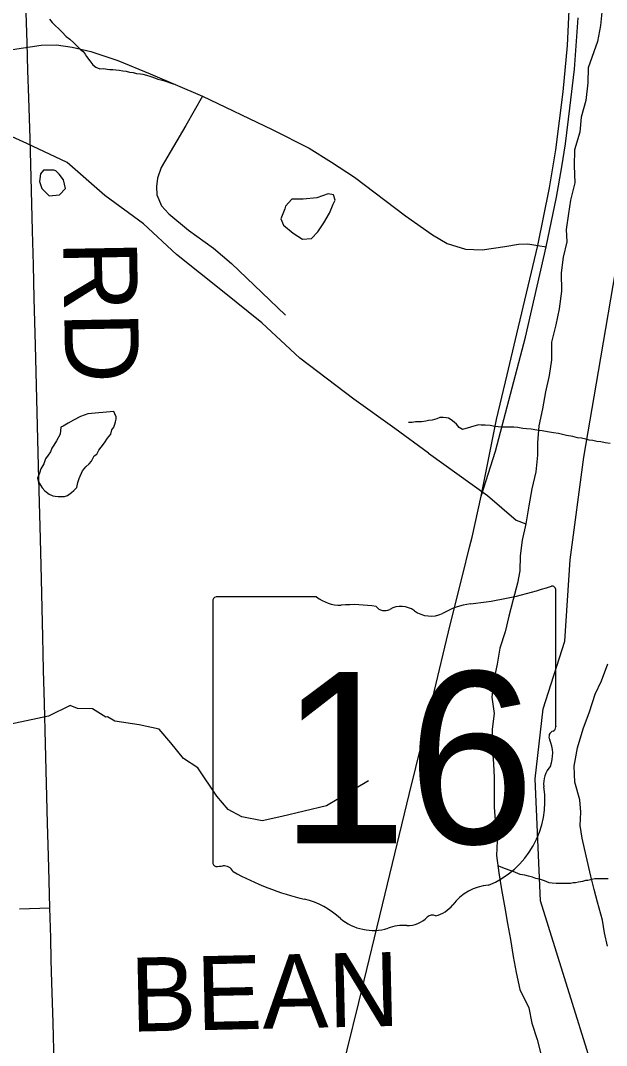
# Model space of a CAD drawing. Extents: x -6.1 to 38, y -7.7 to 22.
# Drawn here: x 4.306 to 4.757, y 15.687 to 16.475 of the extents above; entities that cross this region are included whole.
import ezdxf

# ---------------------------------------------------------------- set-up
doc = ezdxf.new("R2010")
doc.units = 0
for name, color, linetype in [('GM_X_Corporation', 7, 'Continuous'), ('GM_X_County_Road', 7, 'Continuous'), ('GM_X_County_Road_Text', 7, 'Continuous'), ('GM_X_Major_River', 7, 'Continuous'), ('GM_X_Minor_Lake', 7, 'Continuous'), ('GM_X_Minor_River', 7, 'Continuous'), ('GM_X_State_Location', 7, 'Continuous'), ('GM_X_State_Route', 7, 'Continuous'), ('GM_X_State_Shield', 7, 'Continuous'), ('GM_X_Township_Road', 7, 'Continuous'), ('GM_X_Township_Road_Text', 7, 'Continuous')]:
    doc.layers.add(name, color=color, linetype=linetype)

msp = doc.modelspace()

# ---------------------------------------------------------------- linework, layer by layer
at = {"layer": 'GM_X_Corporation'}
for points in [[(4.28061, 14.99995), (5.0967, 14.97556), (5.0486, 15.07962), (5.00913, 15.14194), (4.9572, 15.18142), (4.93228, 15.20843), (4.89329, 15.26962), (4.86101, 15.32821), (4.83828, 15.37125), (4.81915, 15.43553), (4.80087, 15.50695), (4.76612, 15.60524), (4.7059, 15.79844), (4.70175, 15.89192), (4.708, 15.94593), (4.72462, 15.99787), (4.72878, 16.06019), (4.73919, 16.13913), (4.75046, 16.20506), (4.78077, 16.38218), (4.78909, 16.45229), (4.83333, 16.6969)], [(5.74746, 14.95956), (5.18977, 14.97327), (5.0967, 14.97556), (5.0486, 15.07962), (5.00913, 15.14194), (4.9572, 15.18142), (4.93228, 15.20843), (4.89329, 15.26962), (4.86101, 15.32821), (4.83828, 15.37125), (4.81915, 15.43553), (4.80087, 15.50695), (4.76612, 15.60524), (4.7059, 15.79844), (4.70175, 15.89192), (4.708, 15.94593), (4.72462, 15.99787), (4.72878, 16.06019), (4.73919, 16.13913), (4.75046, 16.20506), (4.78077, 16.38218), (4.78909, 16.45229), (4.83333, 16.6969)]]:
    msp.add_lwpolyline(points, dxfattribs=at)
at = {"layer": 'GM_X_County_Road'}
for points in [[(4.33216, 15.67345), (4.33127, 15.70451), (4.33039, 15.73557), (4.3299, 15.75276), (4.32941, 15.76995), (4.32878, 15.79287), (4.32792, 15.82393), (4.32746, 15.841), (4.32699, 15.85806), (4.32615, 15.88853), (4.3253, 15.91899), (4.32459, 15.95005), (4.324, 15.97555), (4.32341, 16.00105), (4.3229, 16.0232), (4.32238, 16.04536), (4.32157, 16.07642), (4.32084, 16.10426), (4.32011, 16.1321), (4.31931, 16.16316), (4.31849, 16.19422), (4.31768, 16.22527), (4.31722, 16.24309), (4.31675, 16.2609), (4.31613, 16.28689), (4.31551, 16.31289), (4.31465, 16.34395), (4.31409, 16.364), (4.31353, 16.38405), (4.31257, 16.41511), (4.31192, 16.43622), (4.31126, 16.45734), (4.31048, 16.48066)], [(4.30002, 16.45221), (4.32205, 16.45572), (4.33381, 16.45579), (4.34597, 16.45406), (4.36018, 16.45075), (4.38106, 16.44372), (4.40589, 16.4337), (4.44615, 16.41641), (4.49966, 16.39096), (4.5281, 16.37638), (4.54515, 16.36572), (4.56291, 16.35412), (4.60225, 16.32448), (4.62287, 16.30981), (4.63409, 16.30318), (4.64837, 16.29885), (4.66111, 16.29834), (4.67846, 16.30088), (4.68905, 16.30263), (4.69609, 16.3031), (4.70391, 16.30184), (4.71026, 16.30082)]]:
    msp.add_lwpolyline(points, dxfattribs=at)
at = {"layer": 'GM_X_Major_River'}
for points in [[(4.75336, 16.48356), (4.75194, 16.47066), (4.74975, 16.45851), (4.74245, 16.43815)], [(4.74245, 16.43815), (4.74217, 16.42678), (4.74077, 16.41312), (4.73709, 16.40021), (4.73605, 16.38883), (4.73201, 16.37516), (4.73173, 16.36303), (4.73222, 16.34976), (4.72892, 16.33647), (4.7275, 16.32623), (4.7257, 16.31409), (4.72616, 16.30461), (4.72323, 16.29284), (4.72182, 16.28071), (4.72193, 16.26668), (4.72016, 16.25303), (4.71761, 16.24088), (4.71432, 16.22759), (4.71443, 16.21394), (4.71264, 16.2018), (4.70972, 16.18928), (4.70755, 16.17637), (4.70464, 16.16309), (4.70361, 16.15019), (4.70369, 16.14071), (4.70228, 16.12782), (4.69936, 16.11491), (4.69682, 16.10163), (4.69467, 16.08797), (4.69175, 16.07544), (4.69034, 16.0633), (4.69005, 16.05193), (4.68824, 16.04244), (4.68494, 16.02991), (4.68164, 16.017), (4.67872, 16.00485), (4.67466, 15.99232), (4.67249, 15.98017), (4.66995, 15.96803), (4.66854, 15.95475), (4.67016, 15.94225), (4.66875, 15.93011), (4.66885, 15.91723), (4.66972, 15.90359), (4.67018, 15.89298), (4.67037, 15.87023), (4.67124, 15.85697), (4.67247, 15.84447), (4.67219, 15.8331), (4.67381, 15.81984), (4.67581, 15.80697), (4.67857, 15.79296), (4.68056, 15.78084), (4.68293, 15.76873), (4.68493, 15.75547), (4.68729, 15.74336), (4.69005, 15.73011), (4.69697, 15.71613), (4.69934, 15.70439), (4.70322, 15.69191), (4.70673, 15.67867)], [(4.75745, 15.76352), (4.7551, 15.77374), (4.7535, 15.78359), (4.74961, 15.79721), (4.74726, 15.80705), (4.74453, 15.81726), (4.741, 15.83278), (4.73786, 15.84641), (4.73627, 15.85625), (4.73694, 15.86649), (4.73611, 15.87596), (4.73222, 15.88958), (4.73174, 15.90171), (4.73427, 15.91575), (4.73869, 15.93056), (4.7435, 15.94348), (4.74792, 15.95716), (4.75275, 15.96742), (4.75756, 15.98034)]]:
    msp.add_lwpolyline(points, dxfattribs=at)
at = {"layer": 'GM_X_Minor_Lake'}
for p, q in [((4.33591, 16.35648), (4.33348, 16.35905)), ((4.50934, 16.3299), (4.50789, 16.32601))]:
    msp.add_line(p, q, dxfattribs=at)
for points in [[(4.33348, 16.35905), (4.33176, 16.35952), (4.32382, 16.35955), (4.32155, 16.3569), (4.32077, 16.35084), (4.32265, 16.34552), (4.32831, 16.33982), (4.33625, 16.34055), (4.3408, 16.34547), (4.33931, 16.3523), (4.33591, 16.35648)], [(4.50789, 16.32601), (4.50637, 16.32222), (4.50824, 16.31729), (4.51579, 16.3112), (4.52296, 16.30663), (4.52977, 16.30699), (4.5347, 16.31228), (4.53926, 16.31909), (4.54381, 16.32666), (4.54648, 16.33348), (4.548, 16.33651), (4.54688, 16.34068), (4.54272, 16.34145), (4.53401, 16.33845), (4.52342, 16.33734), (4.51473, 16.33737), (4.50979, 16.33207), (4.50934, 16.3299)], [(4.37793, 16.17429), (4.35794, 16.17239), (4.35228, 16.17039), (4.34701, 16.16763), (4.34288, 16.16527), (4.33912, 16.16293), (4.33723, 16.16213), (4.33657, 16.15679), (4.334, 16.15181), (4.33179, 16.14835), (4.33031, 16.14604), (4.32922, 16.14336), (4.32736, 16.14066), (4.32552, 16.13797), (4.32406, 16.13414), (4.32185, 16.1303), (4.32078, 16.12686), (4.31933, 16.12303), (4.31975, 16.12075), (4.3217, 16.11775), (4.32288, 16.11548), (4.32482, 16.11324), (4.32828, 16.11064), (4.33096, 16.10955), (4.33287, 16.1092), (4.33515, 16.10886), (4.33819, 16.10892)], [(4.37793, 16.17429), (4.35794, 16.17239), (4.35228, 16.17039), (4.34701, 16.16763), (4.34288, 16.16527), (4.33912, 16.16293), (4.33723, 16.16213), (4.33657, 16.15679), (4.334, 16.15181), (4.33179, 16.14835), (4.33031, 16.14604), (4.32922, 16.14336), (4.32736, 16.14066), (4.32552, 16.13797), (4.32406, 16.13414), (4.32185, 16.1303), (4.32078, 16.12686), (4.31933, 16.12303), (4.31975, 16.12075), (4.3217, 16.11775), (4.32288, 16.11548), (4.32482, 16.11324), (4.32828, 16.11064), (4.33096, 16.10955), (4.33287, 16.1092), (4.33515, 16.10886), (4.33819, 16.10892), (4.34009, 16.10895), (4.34235, 16.10975), (4.34535, 16.11209), (4.34722, 16.11364), (4.34946, 16.11596), (4.35015, 16.11978), (4.35123, 16.12284), (4.35379, 16.12859), (4.35639, 16.13168), (4.35901, 16.13401), (4.36087, 16.13594), (4.3627, 16.14015), (4.36496, 16.14134), (4.36642, 16.1444), (4.36828, 16.14672), (4.37087, 16.15019), (4.37309, 16.15365), (4.37569, 16.15674), (4.37639, 16.16017), (4.37788, 16.1621), (4.37859, 16.16439), (4.37932, 16.16631), (4.37966, 16.16822), (4.37963, 16.17012), (4.37883, 16.17238), (4.37793, 16.17429)], [(4.33819, 16.10892), (4.34009, 16.10895), (4.34235, 16.10975), (4.34535, 16.11209), (4.34722, 16.11364), (4.34946, 16.11596), (4.35015, 16.11978), (4.35123, 16.12284), (4.35379, 16.12859), (4.35639, 16.13168), (4.35901, 16.13401), (4.36087, 16.13594), (4.3627, 16.14015), (4.36496, 16.14134), (4.36642, 16.1444), (4.36828, 16.14672), (4.37087, 16.15019), (4.37309, 16.15365), (4.37569, 16.15674), (4.37639, 16.16017), (4.37788, 16.1621), (4.37859, 16.16439), (4.37932, 16.16631), (4.37966, 16.16822), (4.37963, 16.17012), (4.37883, 16.17238), (4.37793, 16.17429)]]:
    msp.add_lwpolyline(points, dxfattribs=at)
at = {"layer": 'GM_X_Minor_River'}
for points in [[(4.32858, 16.47566), (4.33052, 16.47304), (4.33284, 16.4708), (4.33555, 16.46818), (4.33825, 16.46557), (4.34135, 16.4622), (4.34404, 16.46035), (4.34714, 16.45737), (4.34984, 16.45475), (4.35255, 16.45214), (4.35447, 16.45065), (4.35603, 16.44878), (4.35682, 16.44689), (4.35954, 16.44352), (4.36187, 16.44052), (4.36418, 16.43866), (4.36724, 16.43757), (4.37028, 16.43763), (4.37294, 16.43729), (4.37485, 16.43695), (4.37712, 16.43699), (4.37941, 16.43665), (4.38207, 16.43632), (4.38474, 16.43599), (4.3874, 16.43565), (4.39007, 16.43494), (4.39274, 16.43461), (4.39541, 16.4339), (4.39846, 16.43357), (4.40036, 16.43323), (4.40303, 16.43251), (4.40647, 16.43144), (4.40991, 16.43036), (4.41182, 16.42963), (4.41411, 16.42891), (4.41602, 16.42856), (4.41831, 16.42784), (4.42137, 16.42676), (4.42366, 16.42604), (4.42518, 16.42569)], [(4.6197, 16.14216), (4.59404, 16.1612), (4.56233, 16.18366), (4.52082, 16.21525), (4.49178, 16.24226), (4.46159, 16.26662), (4.42612, 16.29478), (4.40085, 16.31837), (4.37104, 16.34007), (4.34199, 16.36556), (4.31102, 16.38006), (4.27703, 16.39533)], [(4.67069, 16.16279), (4.66726, 16.16349), (4.66345, 16.16381), (4.66042, 16.16375), (4.65813, 16.16409), (4.64604, 16.16045), (4.64336, 16.16193), (4.64141, 16.16455), (4.63949, 16.16604), (4.63718, 16.1679), (4.63526, 16.16901), (4.63335, 16.16935), (4.63107, 16.16969), (4.62841, 16.16964), (4.62615, 16.16846), (4.62275, 16.16764), (4.61972, 16.1672), (4.61782, 16.16679), (4.61442, 16.16635), (4.61214, 16.16631), (4.60986, 16.16627), (4.60721, 16.16584), (4.60531, 16.1658), (4.60493, 16.1658), (4.60455, 16.16579)], [(4.75942, 16.14956), (4.75561, 16.15025), (4.75218, 16.15095), (4.74914, 16.15128), (4.74608, 16.15198), (4.74342, 16.15232), (4.74075, 16.15303), (4.73732, 16.15373), (4.73427, 16.15405), (4.73084, 16.15513), (4.72589, 16.1558), (4.72283, 16.15651), (4.71978, 16.15722), (4.71597, 16.15791), (4.7114, 16.15858), (4.70721, 16.15927), (4.70302, 16.15996), (4.69883, 16.16064), (4.69503, 16.16095), (4.69237, 16.16128), (4.68856, 16.16197), (4.68551, 16.1623), (4.68209, 16.16224), (4.6783, 16.16217), (4.67564, 16.16212), (4.67335, 16.16247), (4.67069, 16.16279)], [(4.6197, 16.14216), (4.66527, 16.10977), (4.68721, 16.09087), (4.69467, 16.08797)], [(4.57364, 15.89053), (4.55092, 15.87695), (4.54145, 15.87129), (4.50702, 15.86305), (4.49188, 15.85968), (4.47639, 15.86276), (4.46581, 15.86848), (4.45714, 15.87874), (4.44246, 15.9004), (4.43151, 15.90764), (4.42171, 15.9198), (4.41266, 15.93007), (4.39754, 15.93353), (4.37864, 15.93624), (4.37298, 15.93966), (4.37185, 15.93929), (4.36165, 15.94576), (4.34993, 15.94618), (4.34427, 15.94847), (4.32761, 15.94018), (4.29393, 15.93307)], [(4.75782, 15.81531), (4.75554, 15.81527), (4.7525, 15.81522), (4.74984, 15.81517), (4.74756, 15.81513), (4.74529, 15.81471), (4.74227, 15.81389), (4.74037, 15.81386), (4.73811, 15.81306), (4.73507, 15.81262), (4.7328, 15.8122), (4.73091, 15.81217), (4.72901, 15.81175), (4.72674, 15.81171), (4.72484, 15.81168), (4.72256, 15.81164), (4.72066, 15.8116), (4.718, 15.81155), (4.71496, 15.81188), (4.71267, 15.81222), (4.71076, 15.81295), (4.70885, 15.81367), (4.70579, 15.81476), (4.70236, 15.81546), (4.69968, 15.81655), (4.69663, 15.81726), (4.69396, 15.81797), (4.69206, 15.81831), (4.69015, 15.81866), (4.68671, 15.82012), (4.68479, 15.82084), (4.6825, 15.82156), (4.67906, 15.82302), (4.67562, 15.8241), (4.67332, 15.8252), (4.67294, 15.82519)]]:
    msp.add_lwpolyline(points, dxfattribs=at)
at = {"layer": 'GM_X_State_Route'}
for points in [[(4.66029, 16.10911), (4.67219, 16.16817), (4.68023, 16.20247), (4.68783, 16.23396), (4.70391, 16.30184), (4.71281, 16.34608), (4.71758, 16.37533), (4.72344, 16.41985), (4.7267, 16.45524), (4.72952, 16.51539)], [(4.71026, 16.30082), (4.71823, 16.33885), (4.72236, 16.36208), (4.72518, 16.37989), (4.72843, 16.40725), (4.73191, 16.43722), (4.73473, 16.47674)], [(4.66029, 16.10911), (4.67132, 16.14385), (4.69435, 16.23136), (4.71026, 16.30082)], [(4.65144, 16.06996), (4.6533, 16.07761), (4.66029, 16.10911)], [(4.50711, 15.47422), (4.51348, 15.49717), (4.52139, 15.53312), (4.53273, 15.57891), (4.54841, 15.64761), (4.56618, 15.72035), (4.58641, 15.80366), (4.60502, 15.8799), (4.61522, 15.92146), (4.62287, 15.95359), (4.63638, 16.01046), (4.64607, 16.04794), (4.65144, 16.06996)]]:
    msp.add_lwpolyline(points, dxfattribs=at)
at = {"layer": 'GM_X_State_Shield'}
for p, q in [((4.53375, 16.03182), (4.45653, 16.03182)), ((4.7176, 15.9321), (4.7176, 16.03678)), ((4.45394, 16.02838), (4.45394, 15.82826)), ((4.71758, 15.93212), (4.7176, 15.9321))]:
    msp.add_line(p, q, dxfattribs=at)
for centre, radius, start, end in [((4.62368, 16.30466), 0.27962, 275.84447, 288.90645), ((4.71468, 16.03722), 0.00294, 351.86209, 97.738), ((4.45696, 16.02881), 0.00305, 98.1301, 188.1301), ((4.55214, 16.05506), 0.02963, 231.61951, 271.11188), ((4.56196, 15.91948), 0.10636, 80.48669, 94.98827), ((4.58611, 16.02985), 0.00855, 219.79206, 297.10237), ((4.59866, 16.00672), 0.01777, 54.46668, 119.14113), ((4.65935, 15.9707), 0.05625, 97.34618, 120.76885), ((4.62159, 16.03844), 0.02138, 233.85621, 294.82819), ((4.71693, 15.92441), 0.00454, 107.94398, 210.33697), ((4.71447, 15.93169), 0.00314, 289.60381, 7.73413), ((4.68803, 15.91118), 0.02727, 340.03296, 23.64957), ((4.72812, 15.88829), 0.01984, 136.8065, 186.92959), ((4.63935, 15.87497), 0.06994, 292.30889, 8.98584), ((4.45699, 15.82782), 0.00308, 171.95839, 258.30661), ((4.45745, 15.8483), 0.02352, 267.33899, 280.60386), ((4.46226, 15.81672), 0.00848, 29.74838, 93.27175), ((4.56932, 15.99652), 0.20192, 240.41292, 257.1985), ((4.66884, 15.77208), 0.0383, 94.40312, 142.57675), ((4.50912, 15.73836), 0.06318, 47.18416, 75.83597), ((4.6203, 15.80887), 0.0226, 282.87319, 323.27711), ((4.62287, 15.78136), 0.00601, 65.75173, 132.64842), ((4.57745, 15.81572), 0.04009, 230.70037, 286.29184), ((4.60062, 15.74653), 0.03294, 85.69512, 111.20995), ((4.60355, 15.80074), 0.02136, 268.77702, 315.54927)]:
    msp.add_arc(centre, radius, start, end, dxfattribs=at)
at = {"layer": 'GM_X_Township_Road'}
for points in [[(4.44615, 16.41641), (4.43336, 16.39391), (4.41442, 16.3617), (4.41157, 16.35341), (4.41086, 16.34702), (4.4111, 16.34062), (4.41465, 16.33233), (4.4201, 16.32617), (4.43526, 16.31362), (4.45444, 16.29965), (4.46842, 16.2878), (4.4857, 16.27123), (4.50986, 16.24825)], [(4.30544, 15.79226), (4.32878, 15.79287)]]:
    msp.add_lwpolyline(points, dxfattribs=at)

# ---------------------------------------------------------------- texts
at = {"layer": 'GM_X_County_Road_Text'}
msp.add_text('RD', height=0.056818, rotation=270.99125, dxfattribs=at).set_placement((4.33889, 16.30537))
at = {"layer": 'GM_X_State_Location'}
for s, p in [('s', (4.5828, 15.91502)), ('r', (4.58279, 15.91502))]:
    msp.add_text(s, height=0.000189, dxfattribs=at).set_placement(p)
msp.add_text('16', height=0.000189, rotation=0.00001, dxfattribs=at).set_placement((4.53511, 15.90124))
at = {"layer": 'GM_X_State_Shield'}
msp.add_text('16', height=0.131836, dxfattribs=at).set_placement((4.50546, 15.84237))
at = {"layer": 'GM_X_Township_Road_Text'}
msp.add_text('BEAN', height=0.056818, rotation=1.25428, dxfattribs=at).set_placement((4.39112, 15.69778))

doc.saveas('drawing.dxf')
